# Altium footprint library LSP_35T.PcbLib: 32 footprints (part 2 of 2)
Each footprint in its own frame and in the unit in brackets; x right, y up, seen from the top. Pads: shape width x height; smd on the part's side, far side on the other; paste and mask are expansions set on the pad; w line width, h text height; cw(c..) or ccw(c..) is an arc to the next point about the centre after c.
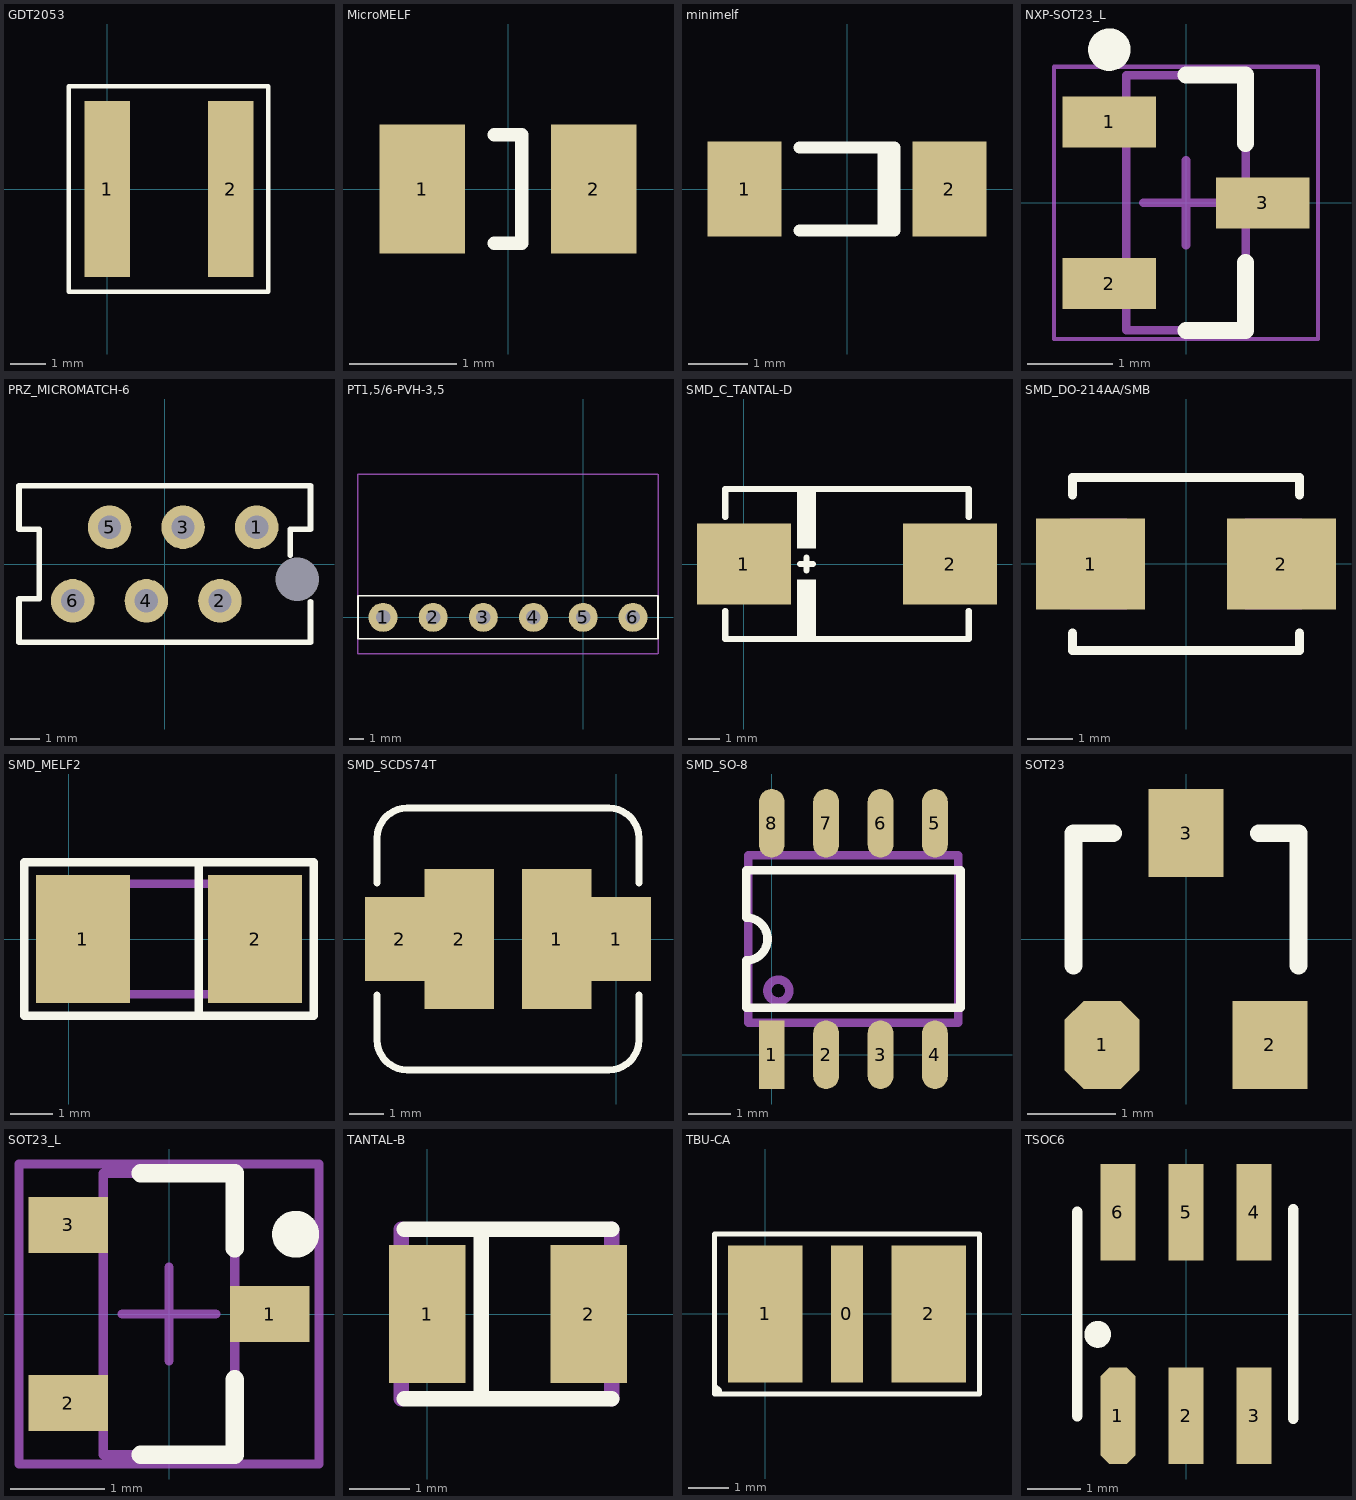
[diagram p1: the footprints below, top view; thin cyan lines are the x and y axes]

## GDT2053 [mil]
height 166
pads (2):
  rect 51x197 smd: 1(0,0) 2(138,0)
Top Overlay:
  lines w5: -43,-115 180,-115 180,115 -43,115 -43,-115

## MicroMELF [mil]
pads (2):
  rect 31.5x47.3 smd: 1(-31.5,0) 2(31.5,0)
Top Overlay:
  lines w5: -5,-20 5,-20 5,20 -5,20

## minimelf [mm] "Metal Electrode Face (MELF) Diode; Body 3.5 x 1.5 mm (LxDia)"
height 1.5
pads (2):
  rect 1.25x1.6 smd: 1(-1.725,0) 2(1.725,0)
Top Overlay:
  lines w0.2: -0.8,-0.7 0.8,-0.7 0.8,0.7 -0.8,0.7 ; 0.61,-0.7 0.61,0.7

## NXP-SOT23_L [mm] "SOT23, 3-Leads, Body 3x1.4mm, Pitch 0.95mm, IPC High Density"
height 1.1
pads (3):
  rect 1.1x0.6 smd: 1(-0.9,0.95) 2(-0.9,-0.95) 3(0.9,0)
Top Overlay:
  circle w0.25: c-0.9,1.8 r0.125
  lines w0.2: 0,-1.5 0.7,-1.5 0.7,-0.7 ; 0,1.5 0.7,1.5 0.7,0.7
Mechanical 13:
  lines w0.1: -0.7,-1.5 0.7,-1.5 0.7,1.5 -0.7,1.5 -0.7,-1.5
Mechanical 15:
  lines w0.05: -1.55,-1.6 1.55,-1.6 1.55,1.6 -1.55,1.6 -1.55,-1.6
  lines w0.1: -0.5,0 0.5,0 ; 0,-0.5 0,0.5
3D body: height 1.1, standoff 0, extent -0.7,-1.5 0.7,1.5

## PRZ_MICROMATCH-6 [mm]
pads (7):
  round 1.5 hole 0.8: 1(3.175,1.27) 2(1.905,-1.27) 3(0.635,1.27) 4(-0.635,-1.27) 5(-1.905,1.27) 6(-3.175,-1.27)
  round 0.8 hole 1.5: ""(4.575,-0.53)
Top Overlay:
  lines w0.2: 4.33,0.3 4.33,1.2 5.03,1.2 5.03,2.7 -5.03,2.7 -5.03,1.2 -4.33,1.2 -4.33,-1.2 -5.03,-1.2 -5.03,-2.7 5.03,-2.7 5.03,-1.3

## PT1,5/6-PVH-3,5 [mil] "Phoenix Contact Terminal"
height 167.32
pads (6):
  round 80 hole 40: 1(-551,0) 2(-413,0) 3(-275,0) 4(-137,0) 5(0,0) 6(137,0)
Top Overlay:
  lines w3.94: -620,-59.06 206,-59.06 ; -620,59.06 206,59.06
  lines w5: -620,-59.06 -620,59.06 ; 206,-59.06 206,59.06
Mechanical 15:
  lines w3.94: 205,-100 -620,-100 -620,393.7 205,393.7 ; 206,-100 206,393.7

## SMD_C_TANTAL-D [mm]
pads (2):
  rect 3x2.6 smd: 1(0,0) 2(6.6,0)
Top Overlay:
  region: 2.3,2.4 1.7,2.4 1.7,0.5 2.3,0.5
  region: 2.3,-0.5 1.7,-0.5 1.7,-2.4 2.3,-2.4
  lines w0.2: -0.6,-1.5 -0.6,-2.4 7.2,-2.4 7.2,-1.5 ; -0.6,1.5 -0.6,2.4 7.2,2.4 7.2,1.5 ; 1.8,0 2.2,0 ; 2,-0.2 2,0.2
Mechanical 2:
  region: 1.1,1.2 -0.55,1.2 -0.55,-1.2 1.1,-1.2
  region: 7.15,1.2 5.5,1.2 5.5,-1.2 7.15,-1.2

## SMD_DO-214AA/SMB [mm]
pads (2):
  rect 2.4x2 smd: 1(-2.1,0) 2(2.1,0)
Top Overlay:
  lines w0.2: -2.5,-1.524 -2.5,-1.9 2.5,-1.9 2.5,-1.524 ; -2.5,1.524 -2.5,1.9 2.5,1.9 2.5,1.524
Mechanical 2:
  rectangle: 1.3,-1 2.55,1
  rectangle: -2.55,-1 -1.3,1

## SMD_MELF2 [mm]
pads (2):
  rect 2.2x3 smd: 1(0.33,0) 2(4.369,0)
Top Overlay:
  lines w0.2: 3.048,-1.797 3.048,1.803 ; -1.05,-1.8 5.75,-1.8 5.75,1.8 -1.05,1.8 -1.05,-1.8
Mechanical 2:
  rectangle: -0.15,-1.4 0.4,1.4
  rectangle: 4.3,-1.4 4.85,1.4
  lines w0.2: 0.15,1.3 4.55,1.3 ; 0.2,-1.3 4.55,-1.3 ; 3.65,-0.7 3.65,0.7

## SMD_SCDS74T [mm]
pads (4):
  rect 2x4 smd: 1(-1.7,0) 2(-4.5,0)
  rect 2x2.4 smd: 1(0,0) 2(-6.2,0)
Top Overlay:
  lines w0.2: -6.85,-1.6 -6.85,-2.9 ccw(c-6,-2.9) -6,-3.75 -0.2,-3.75 ccw(c-0.2,-2.9) 0.65,-2.9 0.65,-1.6 ; -6.85,1.6 -6.85,2.9 cw(c-6,2.9) -6,3.75 -0.2,3.75 cw(c-0.2,2.9) 0.65,2.9 0.65,1.6
Mechanical 2:
  region: -5.6,0.9 -6.8,0.9 -6.8,-0.9 -5.6,-0.9
  region: 0.6,0.9 -0.6,0.9 -0.6,-0.9 0.6,-0.9

## SMD_SO-8 [mm]
pads (8):
  rect 0.6x1.6 smd: 1(0,0)
  oval 0.6x1.6 smd: 2(1.27,0) 3(2.54,0) 4(3.81,0) 5(3.81,5.4) 6(2.54,5.4) 7(1.27,5.4) 8(0,5.4)
Top Overlay:
  lines w0.2: -0.595,1.1 -0.595,2.2 ccw(c-0.595,2.7) -0.595,3.2 -0.595,4.3 4.405,4.3 4.405,1.1 -0.595,1.1
Mechanical 2:
  circle w0.2: c0.155,1.495 r0.255
  region: 1.47,-0.3 1.47,0.75 1.07,0.75 1.07,-0.3
  region: 2.74,-0.3 2.74,0.75 2.34,0.75 2.34,-0.3
  region: 0.2,-0.3 0.2,0.75 -0.2,0.75 -0.2,-0.3
  region: 4.01,-0.3 4.01,0.75 3.61,0.75 3.61,-0.3
  region: 2.34,5.7 2.34,4.65 2.74,4.65 2.74,5.7
  region: 1.07,5.7 1.07,4.65 1.47,4.65 1.47,5.7
  region: 3.61,5.7 3.61,4.65 4.01,4.65 4.01,5.7
  region: -0.2,5.7 -0.2,4.65 0.2,4.65 0.2,5.7
  lines w0.2: -0.545,0.75 4.355,0.75 4.355,4.65 -0.545,4.65 -0.545,0.75

## SOT23 [mm] "SOT-23; 3 Leads; Body 3.0 x 2.5 mm, inc. leads (LxW max)"
height 1.1
pads (3):
  oct 0.85x1 smd: 1(-0.95,-1.2)
  rect 0.85x1 smd: 2(0.95,-1.2) 3(0,1.2)
Top Overlay:
  lines w0.2: -1.275,-0.3 -1.275,1.2 -0.825,1.2 ; 0.825,1.2 1.275,1.2 1.275,-0.3

## SOT23_L [mm] "SOT23, 3-Leads, Body 2.9x1.3mm, Pitch 0.95mm, Lead Span 2.3mm - Reverse Pinning, IPC High Density"
height 1.1
pads (3):
  rect 0.85x0.6 smd: 1(1.075,0) 2(-1.075,-0.95) 3(-1.075,0.95)
Top Overlay:
  circle w0.25: c1.35,0.85 r0.125
  lines w0.2: -0.3,-1.5 0.7,-1.5 0.7,-0.7 ; -0.3,1.5 0.7,1.5 0.7,0.7
Mechanical 13:
  lines w0.1: -0.7,-1.5 0.7,-1.5 0.7,1.5 -0.7,1.5 -0.7,-1.5
Mechanical 15:
  lines w0.1: -0.5,0 0.5,0 ; 0,-0.5 0,0.5 ; -1.6,-1.6 1.6,-1.6 1.6,1.6 -1.6,1.6 -1.6,-1.6
3D body: height 1.1, standoff 0, extent -0.7,-1.5 0.7,1.5

## TANTAL-B [mil]
pads (2):
  rect 50x90 smd: 1(0,0) 2(105,0)
Top Overlay:
  lines w10: -15,-55 120,-55 ; -15,55 120,55 ; 35,-50 35,55
Mechanical 15:
  lines w10: -17,-55 -17,55 ; 120,-55 120,55

## TBU-CA [mil]
height 40
pads (3):
  rect 31x134 smd: 0(80,0)
  rect 73x134 smd: 1(0,0) 2(160,0)
Top Overlay:
  lines w5: -50,-70 -45,-75 ; -50,-78.5 -50,78.5 210,78.5 210,-78.5 -50,-78.5

## TSOC6 [mm] "Small Outline; 6 C-Bend Leads; Body Width 3.8 mm; Pitch 1.27 mm"
height 1.5
pads (6):
  oct 0.65x1.8 smd: 1(-1.27,-1.9)
  rect 0.65x1.8 smd: 2(0,-1.9) 3(1.27,-1.9) 4(1.27,1.9) 5(0,1.9) 6(-1.27,1.9)
Top Overlay:
  circle w0.25: c-1.649,-0.381 r0.125
  lines w0.2: -2.032,-1.905 -2.032,1.905 ; 2,-1.95 2,1.95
